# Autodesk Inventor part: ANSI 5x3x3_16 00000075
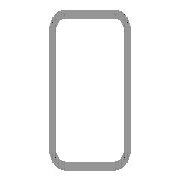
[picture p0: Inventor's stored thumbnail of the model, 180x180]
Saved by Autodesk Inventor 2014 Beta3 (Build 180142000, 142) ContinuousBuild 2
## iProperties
IsCustomPart: 1
Created: 2011-11
Part Number: ANSI 5x3x3_16 00000075
Material: Steel, Mild
Description: Tube
Document SubType Name: Modeling
Standard: ANSI
Designer: Thom Tremblay
Standards Organization: ANSI
Language: en-US
Size Designation: 5x3x3/16
Categories: <MemberInstance><Categories><Category DisplayName="Structural Shapes" InternalName="089c4875-fa83-4c05-b084-43b9cc11f5ed" Mnemonic="GRDR"><CategoryParameter Dis
Stock Number: 5x3x3/16
Density: 7.86 g/cm^3
Appearance: Steel
_CCFamilyMember: 33
_CCFamilyDisplayName: ANSI AISC (Rectangular) - Tube
_FrameMemberDoc: Frame Member File
_Version: 15.0.0
_GetPNFromCC: 1
G_L: 18.747 in
G_W: 3.000 in
G_H: 5.000 in
+CF1ADD6C-EB40-4606-989C-EC2802D0A71C+CUTDETAIL3: Cut
+B2A553CF-D4ED-4223-AC76-4A511DF4A8BA+CUTDETAIL4: Cut
Author: Thom Tremblay
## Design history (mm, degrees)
node "Start plane"
node "End plane"
node "Driven Length"
  sketch "Sketch3"
    geometry: L1 (0, 0)-(10, 0) reference
    constraints: 2 end point, 1 horizontal
  workplane "Work Plane3"
  sketch "Sketch4"
    geometry: L1 (-2, 0)-(12, 0) reference; L2 (-53.343, 476.185)-(53.343, 476.185) reference
    dimensions: "d19" = 476.18539 distance between parallel lines of L1 L2 (derived)
sketch "Sweep Path"
  geometry: L1 through (609.6, 0) direction (-1, -0); 1 other entity
  constraints: 5 horizontal
node "Orientation Work Plane"
feature "Body" dims "d20" = 0
workplane "Work Plane7"
sketch "Sketch7"
  geometry: L1 (-38.6, 64)-(38.6, 64); L2 (-38.6, -64)-(38.6, -64)
  constraints: 4 end point
feature "LoftSrf3" sketch "Sketch7" dims "d29" = 0, "d30" = 90 deg, "d31" = 0, "d32" = 90 deg
split "Split3"
workplane "Work Plane8"
sketch "Sketch8"
  geometry: L1 (-38.6, 64)-(38.6, 64); L2 (-38.6, -64)-(38.6, -64)
  constraints: 4 end point
feature "LoftSrf4" sketch "Sketch8" dims "d33" = 0, "d34" = 90 deg, "d35" = 0, "d36" = 90 deg
split "Split4"
workplane "Work Plane9"
sketch "Sketch9"
  geometry: L1 (-38.6, 73.96)-(38.6, 73.96); L2 (-38.6, -73.96)-(38.6, -73.96)
  constraints: 4 end point
feature "LoftSrf5" sketch "Sketch9" dims "d37" = 0, "d38" = 90 deg, "d39" = 0, "d40" = 90 deg
split "Split5"
workplane "Work Plane10"
sketch "Sketch10"
  geometry: L1 (-38.6, 73.96)-(38.6, 73.96); L2 (-38.6, -73.96)-(38.6, -73.96)
  constraints: 4 end point
feature "LoftSrf6" sketch "Sketch10" dims "d41" = 0, "d42" = 90 deg, "d43" = 0, "d44" = 90 deg
split "Split6"
body "Solid1"
sketch "Sketch"
  geometry: L1 (-38.1, -53.975)-(-38.1, 53.975); L2 (-28.575, 63.5)-(28.575, 63.5); L3 (38.1, 53.975)-(38.1, -53.975); L4 (28.575, -63.5)-(-28.575, -63.5); L5 (-28.575, 58.737)-(28.575, 58.737); L6 (33.338, 53.975)-(33.338, -53.975); L7 (28.575, -58.737)-(-28.575, -58.737); L8 (-33.338, -53.975)-(-33.338, 53.975); L9 (0, 36.948)-(0, -36.948); L10 (-23.079, 0)-(23.079, 0); A1 r 9.525 centre (-28.575, -53.975) between (-38.1, -53.975) and (-28.575, -63.5); A2 r 9.525 centre (-28.575, 53.975) between (-28.575, 63.5) and (-38.1, 53.975); A3 r 9.525 centre (28.575, 53.975) between (38.1, 53.975) and (28.575, 63.5); A4 r 9.525 centre (28.575, -53.975) between (28.575, -63.5) and (38.1, -53.975); A5 r 4.763 centre (-28.575, 53.975) between (-28.575, 58.737) and (-33.338, 53.975); A6 r 4.763 centre (28.575, 53.975) between (33.338, 53.975) and (28.575, 58.737); A7 r 4.763 centre (28.575, -53.975) between (28.575, -58.737) and (33.338, -53.975); A8 r 4.763 centre (-28.575, -53.975) between (-33.338, -53.975) and (-28.575, -58.737)
  constraints: 20 end point, 16 point on circle, 8 centre point, 8 tangent, 4 parallel, 3 equal radius, 2 perpendicular, 7 other
  dimensions: "d10" = 127 distance between parallel lines of L2 L4 (= G_H); "d11" = 76.2 distance between parallel lines of L1 L3 (= G_W); "d12" = 4.7625 distance between parallel lines of L3 L6 (= G_T); "d15" = 63.5 distance between parallel lines of L2 L10 (= 0.5 x d10); "d16" = 38.1 distance between parallel lines of L9 L3 (= 0.5 x d11); "d17" = 9.525 radius of A1 (= G_IR)
body "Srf3"
body "Srf4"
body "Srf5"
body "Srf6"
other parameters: "G_W" = 76.2 [user parameter; used in 1 equation term], "G_H" = 127 [user parameter; used in 1 equation term], "G_T" = 4.7625 [user parameter; used in 1 equation term], "G_IR" = 9.525 [user parameter; used in 1 equation term], "G_L" = 476.18539 (= d19) [user parameter], "G_OFFSET_START" = 0 [user parameter; used in 1 equation term], "G_OFFSET_END" = 0 [user parameter; used in 1 equation term], "d13" = 0 (computed from G_OFFSET_START), "d14" = 476.18539 (= G_OFFSET_END + B_L), "B_L" = 476.18539 [user parameter; used in 1 equation term], "d18" = 90 deg
